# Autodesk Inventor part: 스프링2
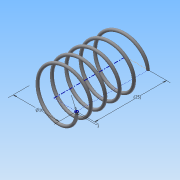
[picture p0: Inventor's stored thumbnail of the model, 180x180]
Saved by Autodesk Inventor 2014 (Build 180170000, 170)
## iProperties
Created: 2015-06
Part Number: 스프링2
Material: 강철, 연강
Document SubType Name: Modeling
Designer: Administrator
Density: 7.86 g/cm^3
Appearance: 강철
Mass: 1.53479 g
Surface Area: 7.89194 cm^2
Volume: 0.195266 cm^3
Author: Administrator
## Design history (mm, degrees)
sketch "스케치1"
  geometry: L1 (0, 0)-(8, 0); L2 (8, 0)-(8, 21.5); L3 (8, 21.5)-(0, 21.5); L4 (0, 21.5)-(0, 0); C1 r 0.5 at (8, 0)
  constraints: 8 end point, 2 parallel, 1 centre point, 1 coincident, 1 horizontal, 1 perpendicular
  dimensions: "d0" = 21.5 distance of L1.end L2.end (derived); "d1" = 16 diameter of L2 L4; "d2" = 1 diameter of C1
feature "코일1" sketch "스케치1" pitch "d3" = 10; turns "d5" = 5; dims "d4" = 21.5 (= d0), "d6" = 0, angle "d7" = 90 deg, angle "d8" = 90 deg, "d9" = 0, "d10" = 0
sketch "스케치2"
  geometry: L1 (-8.5, 0)-(-7.5, 0) reference; 1 further point
  constraints: 1 horizontal alignment
extrude "돌출1" cut sketch "스케치2" stored distance "d11" = 10; taper "d12" = 0 deg
node "작업 평면1"
sketch "스케치3"
  geometry: L1 (-7.5, 0)-(-8.5, 0) reference; 1 further point
  constraints: 1 horizontal alignment
extrude "돌출2" cut sketch "스케치3" stored distance "d14" = 10; taper "d15" = 0 deg
node "솔리드1"
node "절단 모서리 투영1"
node "절단 모서리 투영2"
other parameters: "d13" = 21.5 (= d0)
